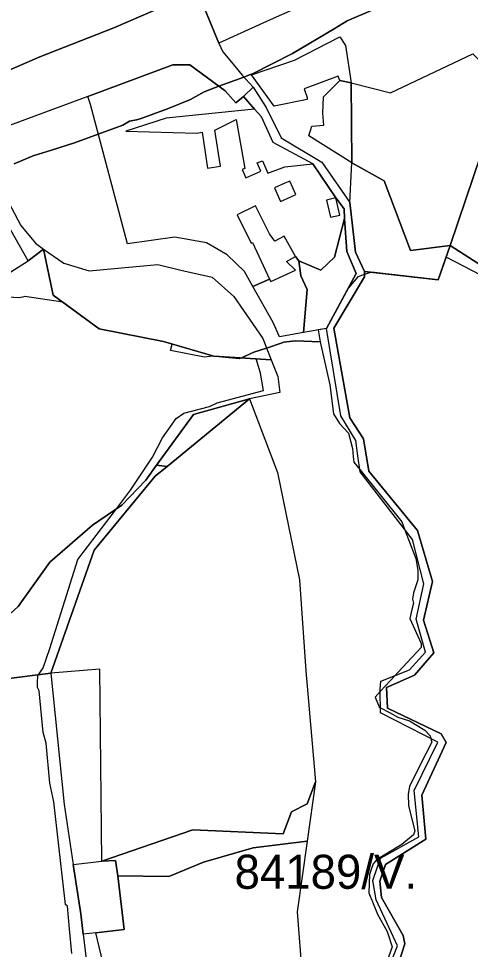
# Model space of a CAD drawing. Extents: x -477304 to -465429, y -1159113 to -1149210.
# Drawn here: x -472999.7 to -472801, y -1154296.2 to -1153886.3 of the extents above; entities that cross this region are included whole.
import ezdxf

# ---------------------------------------------------------------- set-up
doc = ezdxf.new("R2010")
doc.units = 0
for name, color, linetype in [('BPEJ_s', 7, 'Continuous'), ('orna_s', 7, 'Continuous'), ('PUPFL_s', 7, 'Continuous'), ('trav_porost_s', 7, 'Continuous'), ('voda_s', 7, 'Continuous'), ('zahrada_s', 7, 'Continuous')]:
    doc.layers.add(name, color=color, linetype=linetype)

msp = doc.modelspace()

# ---------------------------------------------------------------- linework, layer by layer
at = {"layer": 'BPEJ_s'}
for points in [[(-473001.73, -1153950.22), (-472993.01, -1153946.6), (-472992.88, -1153946.56), (-472985.22, -1153944.19), (-472975.14, -1153941.07), (-472964.69, -1153937.2), (-472953.86, -1153933.19), (-472950.88, -1153931.49), (-472947.91, -1153930.82), (-472946.19, -1153930.43), (-472934.28, -1153925.96), (-472924.07, -1153921.92), (-472918.11, -1153918.51), (-472911.59, -1153916.1), (-472900.66, -1153912.06), (-472898.08, -1153911.1), (-472896.83, -1153910.64), (-472879.17, -1153901.7), (-472860.93, -1153890.73), (-472855.13, -1153887.23), (-472843.21, -1153882.13)], [(-472843.21, -1153882.13), (-472855.13, -1153887.23), (-472860.93, -1153890.73), (-472879.17, -1153901.7), (-472896.83, -1153910.64), (-472898.08, -1153911.1), (-472900.66, -1153912.06), (-472911.59, -1153916.1), (-472918.11, -1153918.51), (-472924.07, -1153921.92), (-472934.28, -1153925.96), (-472946.19, -1153930.43), (-472947.91, -1153930.82), (-472950.88, -1153931.49), (-472953.86, -1153933.19), (-472964.69, -1153937.2), (-472975.14, -1153941.07), (-472985.22, -1153944.19), (-472992.88, -1153946.56), (-472993.01, -1153946.6), (-473001.73, -1153950.22)], [(-472796.43, -1153999.26), (-472811.59, -1153991.29), (-472815.15, -1154001.3), (-472844.47, -1153998), (-472847.53, -1153999.01), (-472850.53, -1154000), (-472854.6, -1154004.83), (-472864.21, -1154022.74), (-472867.98, -1154023.41), (-472867.1, -1154028.56), (-472877.93, -1154028.21), (-472883.25, -1154028.85)], [(-472796.43, -1153999.26), (-472811.59, -1153991.29), (-472815.15, -1154001.3), (-472844.47, -1153998), (-472847.53, -1153999.01), (-472850.53, -1154000), (-472854.6, -1154004.83), (-472864.21, -1154022.74), (-472867.98, -1154023.41), (-472867.1, -1154028.56), (-472862.83, -1154047.56), (-472861.13, -1154060.32), (-472858.58, -1154064.57)], [(-472883.25, -1154028.85), (-472883.79, -1154029.03), (-472890.67, -1154031.35), (-472896.2, -1154033.21), (-472901.89, -1154035.76), (-472902.19, -1154035.89), (-472902.59, -1154036.08), (-472908.88, -1154035.52), (-472914.5, -1154035.01), (-472917.91, -1154035.44), (-472932.84, -1154032.45), (-472932.12, -1154029.59), (-472935.97, -1154028.45), (-472964.26, -1154022.87), (-472980.33, -1154011.15), (-472997.01, -1154008.65), (-472998.07, -1154008.91), (-472999.56, -1154009.28), (-473019.12, -1154008.01)], [(-472991.48, -1154180.88), (-472991.4, -1154178.87), (-472991.26, -1154175.57), (-472991.11, -1154175.34), (-472991.05, -1154175.25), (-472988.93, -1154172.16), (-472985.95, -1154163.66), (-472973.62, -1154124.53), (-472956.73, -1154102.22), (-472950.44, -1154093.91), (-472940.87, -1154079.45), (-472936.41, -1154070.95), (-472930.45, -1154062.44), (-472927.05, -1154060.1), (-472915.78, -1154057.13), (-472912.38, -1154055.43), (-472892.03, -1154050.1), (-472893.24, -1154042.46), (-472895.25, -1154036.19), (-472899.05, -1154035.94), (-472901.89, -1154035.76), (-472902.19, -1154035.89), (-472902.59, -1154036.08), (-472908.88, -1154035.52), (-472914.5, -1154035.01), (-472917.91, -1154035.44), (-472932.84, -1154032.45), (-472932.12, -1154029.59), (-472935.97, -1154028.45), (-472964.26, -1154022.87), (-472980.33, -1154011.15), (-472997.01, -1154008.65), (-472998.07, -1154008.91), (-472999.56, -1154009.28), (-473019.12, -1154008.01)], [(-472987.65, -1154205.34), (-472988.93, -1154200.66), (-472990.63, -1154182.37), (-472991.48, -1154180.88), (-472991.4, -1154178.87), (-472991.26, -1154175.57), (-472991.11, -1154175.34), (-472991.05, -1154175.25), (-472988.93, -1154172.16), (-472985.95, -1154163.66), (-472973.62, -1154124.53), (-472956.73, -1154102.22), (-472950.44, -1154093.91), (-472940.87, -1154079.45), (-472936.41, -1154070.95), (-472930.45, -1154062.44), (-472927.05, -1154060.1), (-472915.78, -1154057.13), (-472912.38, -1154055.43), (-472892.03, -1154050.1), (-472893.24, -1154042.46), (-472895.25, -1154036.19), (-472899.05, -1154035.94), (-472901.89, -1154035.76), (-472896.2, -1154033.21), (-472890.67, -1154031.35), (-472883.79, -1154029.03), (-472883.25, -1154028.85), (-472877.93, -1154028.21), (-472867.1, -1154028.56)], [(-472867.1, -1154028.56), (-472862.83, -1154047.56), (-472861.13, -1154060.32), (-472858.58, -1154064.57), (-472854.54, -1154068.82), (-472852.84, -1154075.63), (-472852.47, -1154079.09), (-472852.2, -1154081.58), (-472849.62, -1154084.82), (-472831.15, -1154107.95), (-472829.93, -1154111.14), (-472824.98, -1154124.11), (-472824.13, -1154129.21), (-472824.13, -1154133.46), (-472826.05, -1154139.21), (-472826.47, -1154141.97), (-472826.05, -1154143.67), (-472826.67, -1154146.52), (-472827.53, -1154150.48), (-472822.64, -1154161.53), (-472822.64, -1154163.23), (-472832.85, -1154174.29), (-472834.08, -1154175.62), (-472840.6, -1154182.69), (-472842.8, -1154185.07), (-472841.14, -1154189.39), (-472840.48, -1154189.75), (-472836.49, -1154191.89), (-472832.85, -1154193.85), (-472827.75, -1154195.55), (-472820.94, -1154199.59), (-472818.6, -1154202.15), (-472818.31, -1154203.43), (-472818.18, -1154203.99), (-472817.96, -1154204.91), (-472823.14, -1154215.26), (-472827.75, -1154224.47), (-472828.39, -1154227.88), (-472828.17, -1154232.98), (-472825.41, -1154244.04), (-472826.05, -1154245.74), (-472831.15, -1154249.99), (-472842.21, -1154256.79), (-472843.39, -1154258.15), (-472843.69, -1154258.5), (-472844.61, -1154261.02), (-472845.4, -1154263.17), (-472845.61, -1154271.25), (-472841.78, -1154280.61), (-472837.53, -1154288.26), (-472835.4, -1154295.07), (-472839.87, -1154307.83)], [(-472858.58, -1154064.57), (-472854.54, -1154068.82), (-472852.84, -1154075.63), (-472852.47, -1154079.09), (-472852.2, -1154081.58), (-472849.62, -1154084.82), (-472831.15, -1154107.95), (-472829.93, -1154111.14), (-472824.98, -1154124.11), (-472824.13, -1154129.21), (-472824.13, -1154133.46), (-472826.05, -1154139.21), (-472826.47, -1154141.97), (-472826.05, -1154143.67), (-472826.67, -1154146.52), (-472827.53, -1154150.48), (-472822.64, -1154161.53), (-472822.64, -1154163.23), (-472832.85, -1154174.29), (-472834.08, -1154175.62), (-472840.6, -1154182.69), (-472842.8, -1154185.07), (-472841.14, -1154189.39), (-472840.48, -1154189.75), (-472836.49, -1154191.89), (-472832.85, -1154193.85), (-472827.75, -1154195.55), (-472820.94, -1154199.59), (-472818.6, -1154202.15), (-472818.31, -1154203.43), (-472818.18, -1154203.99), (-472817.96, -1154204.91), (-472823.14, -1154215.26), (-472827.75, -1154224.47), (-472828.39, -1154227.88), (-472828.17, -1154232.98), (-472825.41, -1154244.04), (-472826.05, -1154245.74), (-472831.15, -1154249.99), (-472842.21, -1154256.79), (-472843.39, -1154258.15), (-472843.69, -1154258.5), (-472844.61, -1154261.02), (-472845.4, -1154263.17), (-472845.61, -1154271.25), (-472841.78, -1154280.61), (-472837.53, -1154288.26), (-472835.4, -1154295.07), (-472839.87, -1154307.83)], [(-472976.28, -1154298.04), (-472977.34, -1154287.13), (-472978.3, -1154277.21), (-472978.93, -1154276.57), (-472979.14, -1154276.36), (-472984.25, -1154231.28), (-472985.95, -1154222.98), (-472987.65, -1154205.34), (-472988.93, -1154200.66), (-472990.63, -1154182.37), (-472991.48, -1154180.88)], [(-472976.28, -1154298.04), (-472977.34, -1154287.13), (-472978.3, -1154277.21), (-472978.93, -1154276.57), (-472979.14, -1154276.36), (-472984.25, -1154231.28), (-472985.95, -1154222.98), (-472987.65, -1154205.34)]]:
    msp.add_lwpolyline(points, dxfattribs=at)
at = {"layer": 'orna_s'}
msp.add_lwpolyline([(-472827.26, -1153988.46), (-472838.92, -1153957.74), (-472853.13, -1153949.74), (-472853.4, -1153914.56), (-472836.18, -1153919.04), (-472799.95, -1153901.78), (-472786, -1153915.46), (-472809.81, -1153986.28)], close=True, dxfattribs=at)
at = {"layer": 'PUPFL_s'}
for points in [[(-473028.58, -1154013.8), (-472995.53, -1153992.99), (-472988.79, -1153987.76), (-472984.49, -1154008.11), (-472964.26, -1154022.87), (-472935.97, -1154028.45), (-472913.88, -1154035), (-472888.58, -1154036.61), (-472885.69, -1154043.9), (-472884.83, -1154050.9), (-472898.18, -1154053.7), (-472922.79, -1154060.6), (-472939.03, -1154083), (-472943.73, -1154089.62), (-472954.27, -1154100.56), (-472967.29, -1154109.37), (-472985.98, -1154125.69), (-472999.88, -1154145.17)], [(-472833.81, -1154306.11), (-472829.81, -1154293.73), (-472830.58, -1154290.05), (-472840.13, -1154273.36), (-472840.79, -1154266.21), (-472838.34, -1154258.74), (-472820.51, -1154247.63), (-472822.37, -1154228.2), (-472811.6, -1154205.15), (-472813.85, -1154201.26), (-472837.5, -1154189.94), (-472837.81, -1154180.81), (-472825.5, -1154175.49), (-472817.11, -1154165.54), (-472821.53, -1154151.22), (-472817.57, -1154134.23), (-472824.3, -1154111.78), (-472845.6, -1154085.63), (-472847.99, -1154071.36), (-472854.02, -1154062.04), (-472861.04, -1154022.61), (-472847.5, -1154000.03), (-472847.57, -1153997.65), (-472815.15, -1154001.3), (-472809.81, -1153986.28), (-472787.72, -1154000.44)], [(-473202.08, -1154333.7), (-473192.34, -1154285.76), (-473180.59, -1154251.27), (-473170.89, -1154246.71), (-473014.5, -1154178.21), (-472985.59, -1154174.56), (-472979.68, -1154232.42), (-472975.68, -1154258.78), (-472972.38, -1154280.5), (-472971.3, -1154289.5), (-472964.39, -1154346.9)]]:
    msp.add_lwpolyline(points, dxfattribs=at)
for points in [[(-472939.6, -1154087.83), (-472966.52, -1154120.43), (-472985.59, -1154174.56), (-473014.5, -1154178.21), (-473015.58, -1154176.17), (-473017.49, -1154164.82), (-473010.66, -1154154.9), (-472999.88, -1154145.17), (-472985.98, -1154125.69), (-472967.29, -1154109.37), (-472954.27, -1154100.56), (-472943.73, -1154089.62), (-472939.03, -1154083), (-472934.33, -1154083.49)], [(-472953.28, -1154287.48), (-472965.81, -1154288.88), (-472971.3, -1154289.5), (-472972.38, -1154280.5), (-472975.68, -1154258.78), (-472963.19, -1154257.3), (-472957.17, -1154256.98), (-472956.15, -1154263.81)]]:
    msp.add_lwpolyline(points, close=True, dxfattribs=at)
at = {"layer": 'trav_porost_s'}
for points in [[(-473003.97, -1153909.06), (-473041.46, -1153830.37), (-473036.13, -1153828.26), (-473027.67, -1153824.9), (-473010.01, -1153818.51), (-472999.67, -1153814.52), (-472996.28, -1153813.54), (-472967.11, -1153868.16), (-472954.17, -1153862.2), (-472950.5, -1153860.5), (-472941.3, -1153878.79), (-472939.44, -1153882.49), (-472957.82, -1153890.36), (-472990.37, -1153903.15)], [(-472858.43, -1153913.53), (-472859.11, -1153911.65), (-472874.13, -1153917.17), (-472872.75, -1153920.97), (-472872.74, -1153921.86), (-472887.24, -1153924.88), (-472897.25, -1153911.08), (-472878.29, -1153904.62), (-472858.47, -1153894.37), (-472855.97, -1153898.08), (-472853.4, -1153914.56)], [(-472853.4, -1153914.56), (-472853.13, -1153949.74), (-472872.01, -1153937.98), (-472870.71, -1153933.59), (-472865.47, -1153933.18), (-472865.87, -1153928), (-472865.62, -1153920.68), (-472858.43, -1153913.53)], [(-472787.72, -1154000.44), (-472809.81, -1153986.28), (-472786, -1153915.46), (-472753.13, -1153945.89)], [(-472992.35, -1153985.25), (-472988.79, -1153987.76), (-472995.53, -1153992.99), (-473005.04, -1153976.05), (-473003.37, -1153975.26), (-473019.15, -1153944.13), (-473016.95, -1153942.31), (-473011.35, -1153953.78), (-472998.78, -1153977.33)], [(-472815.15, -1154001.3), (-472847.57, -1153997.65), (-472851.54, -1153989.1), (-472853.99, -1153967.34), (-472853.13, -1153949.74), (-472838.92, -1153957.74), (-472827.26, -1153988.46), (-472809.81, -1153986.28)], [(-472864.21, -1154022.74), (-472874.34, -1154024.54), (-472872.71, -1154005.52), (-472875.55, -1153999.6), (-472876.37, -1153992.91), (-472866.75, -1153997.05), (-472860.79, -1153991.3), (-472856.28, -1153974.39), (-472855.39, -1153988.81), (-472851.23, -1153998.56)], [(-472968.72, -1153997.36), (-472938.44, -1153994.65), (-472928.33, -1153997.08), (-472914.57, -1154000.18), (-472905.11, -1154008.65), (-472892.35, -1154027.12), (-472888.58, -1154036.61), (-472913.88, -1154035), (-472935.97, -1154028.45), (-472964.26, -1154022.87), (-472984.49, -1154008.11), (-472988.79, -1153987.76), (-472979.84, -1153994.06)], [(-472966.52, -1154120.43), (-472939.6, -1154087.83), (-472934.33, -1154083.49), (-472898.18, -1154053.7), (-472885.88, -1154086.14), (-472876.21, -1154133.46), (-472873.31, -1154173.48), (-472869.12, -1154222.34), (-472872.72, -1154232.12), (-472879.7, -1154235.67), (-472883.35, -1154245.37), (-472923.11, -1154243.52), (-472963.19, -1154257.3), (-472964.05, -1154172.75), (-472985.59, -1154174.56)], [(-472939.03, -1154083), (-472922.79, -1154060.6), (-472898.18, -1154053.7), (-472934.33, -1154083.49)], [(-472879.7, -1154235.67), (-472872.72, -1154232.12), (-472869.12, -1154222.34), (-472872.82, -1154248.6), (-472896.57, -1154251.42), (-472918.33, -1154257.71), (-472933.69, -1154264.02), (-472956.15, -1154263.81), (-472957.17, -1154256.98), (-472963.19, -1154257.3), (-472923.11, -1154243.52), (-472883.35, -1154245.37)], [(-472953.28, -1154287.48), (-472956.15, -1154263.81), (-472933.69, -1154264.02), (-472918.33, -1154257.71), (-472896.57, -1154251.42), (-472872.82, -1154248.6), (-472877.2, -1154279.68), (-472874.92, -1154308.19), (-472873.71, -1154314.49), (-472924.26, -1154325.38), (-472929.15, -1154327.02), (-472931.2, -1154338.95), (-472933.87, -1154339.66), (-472933.45, -1154337.95), (-472953.65, -1154340), (-472965.81, -1154288.88)]]:
    msp.add_lwpolyline(points, close=True, dxfattribs=at)
at = {"layer": 'voda_s'}
msp.add_lwpolyline([(-472889.06, -1153886.9), (-472911.67, -1153897.1), (-472920.89, -1153874.49), (-472900.85, -1153865.45), (-472887.67, -1153858.9), (-472879.05, -1153882.37)], close=True, dxfattribs=at)
for points in [[(-472920.89, -1153874.49), (-472911.67, -1153897.1), (-472909.87, -1153900.98), (-472905.35, -1153906.41), (-472901.44, -1153911.2), (-472896.59, -1153916.54), (-472900.76, -1153920.53), (-472904.17, -1153923.33), (-472908.84, -1153918.11), (-472924.45, -1153906.68), (-472931.87, -1153906.63), (-472969.34, -1153920.54), (-473007.78, -1153934.81)], [(-473126.13, -1153884.73), (-473150.73, -1153913.41), (-473180.32, -1154028.3), (-473183.77, -1154049.68), (-473179.94, -1154046.8), (-473167.68, -1154037.05), (-473115.44, -1153994.7), (-473096.93, -1153980.22), (-473036.89, -1153929.77), (-473026.93, -1153921.88), (-473020.91, -1153917.11), (-473003.97, -1153909.06), (-472990.37, -1153903.15), (-472957.82, -1153890.36), (-472939.44, -1153882.49)], [(-472838.2, -1154307.72), (-472833.08, -1154294.59), (-472842.41, -1154274.41), (-472843.81, -1154265.84), (-472840.44, -1154256.02), (-472823.67, -1154246.68), (-472825.67, -1154226.16), (-472815.32, -1154204.98), (-472840.44, -1154191.97), (-472840.62, -1154181.74), (-472840.4, -1154178.1), (-472827.68, -1154173.11), (-472820.69, -1154165.29), (-472824.75, -1154150.78), (-472821.44, -1154135.2), (-472826.39, -1154115.72), (-472849.47, -1154085.86), (-472850.45, -1154078.85), (-472851.39, -1154072.14), (-472857.94, -1154061.23), (-472864.21, -1154022.74), (-472851.23, -1153998.56), (-472855.39, -1153988.81), (-472856.28, -1153974.39), (-472856.55, -1153970.09), (-472860.15, -1153965.22), (-472870.29, -1153950.21), (-472887.75, -1153940.9), (-472892.91, -1153929.56), (-472895.91, -1153926.1), (-472900.76, -1153920.53), (-472896.59, -1153916.54), (-472890.76, -1153925.45), (-472884.18, -1153938.74), (-472866.34, -1153949.58), (-472853.99, -1153967.34), (-472851.54, -1153989.1), (-472847.57, -1153997.65), (-472847.5, -1154000.03), (-472861.04, -1154022.61), (-472854.02, -1154062.04), (-472847.99, -1154071.36), (-472845.6, -1154085.63), (-472824.3, -1154111.78), (-472817.57, -1154134.23), (-472821.53, -1154151.22), (-472817.11, -1154165.54), (-472825.5, -1154175.49), (-472837.81, -1154180.81), (-472837.5, -1154189.94), (-472813.85, -1154201.26), (-472811.6, -1154205.15), (-472822.37, -1154228.2), (-472820.51, -1154247.63), (-472838.34, -1154258.74), (-472840.79, -1154266.21), (-472840.13, -1154273.36), (-472830.58, -1154290.05), (-472829.81, -1154293.73), (-472833.81, -1154306.11)]]:
    msp.add_lwpolyline(points, dxfattribs=at)
at = {"layer": 'zahrada_s'}
for points in [[(-472952.63, -1153935.82), (-472921.36, -1153936.68), (-472918.99, -1153936.33), (-472916.62, -1153952.15), (-472910.89, -1153951.3), (-472913.35, -1153935.49), (-472904.06, -1153930.65), (-472900.19, -1153952.24), (-472901.38, -1153952.76), (-472899.77, -1153956.44), (-472893.13, -1153953.54), (-472894.74, -1153949.86), (-472892.45, -1153948.86), (-472890.06, -1153954.42), (-472882.62, -1153951.58), (-472870.29, -1153950.21), (-472860.15, -1153965.22), (-472864.29, -1153966.18), (-472862.52, -1153973.78), (-472858.38, -1153972.81), (-472860.15, -1153965.22), (-472856.55, -1153970.09), (-472856.28, -1153974.39), (-472860.79, -1153991.3), (-472866.75, -1153997.05), (-472876.37, -1153992.91), (-472877.87, -1153991.01), (-472882.92, -1153982.03), (-472887.02, -1153984.33), (-472889.38, -1153981.12), (-472895.52, -1153968.76), (-472903.58, -1153972.77), (-472897.44, -1153985.13), (-472896.9, -1153984.86), (-472889.28, -1154001.06), (-472896.71, -1154004.25), (-472900.42, -1153997.66), (-472908.02, -1153990.35), (-472917.14, -1153985.05), (-472930.97, -1153982.57), (-472951.83, -1153985.53), (-472968.17, -1153924.1), (-472969.34, -1153920.54), (-472931.87, -1153906.63), (-472924.45, -1153906.68), (-472908.84, -1153918.11), (-472904.17, -1153923.33), (-472900.76, -1153920.53), (-472895.91, -1153926.1), (-472934.79, -1153930.07)], [(-472884.54, -1153966.77), (-472879.92, -1153964.74), (-472877.81, -1153963.82), (-472880.42, -1153957.83), (-472882.55, -1153958.75), (-472887.2, -1153960.78)], [(-472872.71, -1154005.52), (-472874.34, -1154024.54), (-472884.95, -1154026.43), (-472887.77, -1154020.15), (-472896.71, -1154004.25), (-472889.28, -1154001.06), (-472888.81, -1154002.06), (-472877.92, -1153997.02), (-472881.88, -1153993.26), (-472877.87, -1153991.01), (-472876.37, -1153992.91), (-472875.55, -1153999.6)]]:
    msp.add_lwpolyline(points, close=True, dxfattribs=at)

# ---------------------------------------------------------------- texts
at = {"layer": 'BPEJ_s'}
msp.add_text('84189/V.', height=15, dxfattribs=at).set_placement((-472904.72, -1154269.51))

doc.saveas('drawing.dxf')
